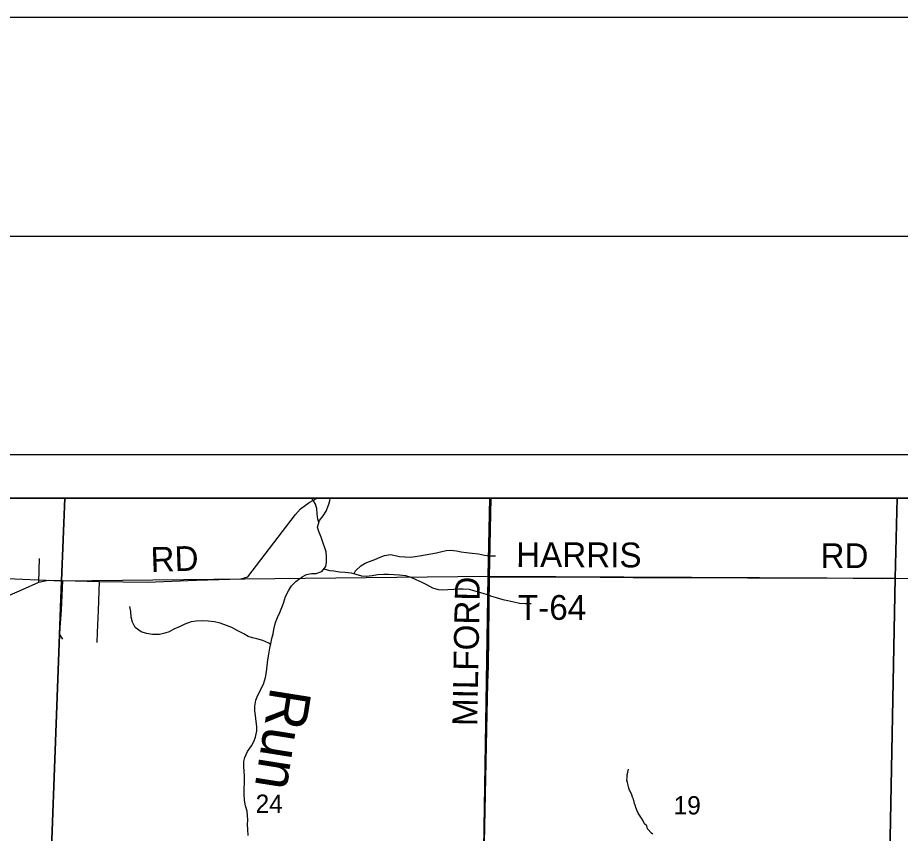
# Model space of a CAD drawing. Extents: x 0 to 34, y 0 to 22.
# Drawn here: x 5.004 to 7.025, y 20.132 to 22 of the extents above; entities that cross this region are included whole.
import ezdxf

# ---------------------------------------------------------------- set-up
doc = ezdxf.new("R2010")
doc.units = 0
for name, color, linetype in [('Default', 7, 'Continuous'), ('GM_X_Minor_River', 7, 'Continuous'), ('GM_X_Minor_River_Text', 7, 'Continuous'), ('GM_X_Section', 7, 'Continuous'), ('GM_X_Section_Text', 7, 'Continuous'), ('GM_X_Township_Road', 7, 'Continuous'), ('GM_X_Township_Road_Text', 7, 'Continuous'), ('SH_Border', 7, 'Continuous'), ('SH_Cut_Line', 7, 'Continuous'), ('SH_Data', 7, 'Continuous')]:
    doc.layers.add(name, color=color, linetype=linetype)

msp = doc.modelspace()

# ---------------------------------------------------------------- linework, layer by layer
at = {"layer": 'Default'}
msp.add_lwpolyline([(4.98, 17.7015), (5.0396, 17.6997), (5.1253, 17.6972), (5.2207, 17.6942), (5.2737, 17.6923), (5.3125, 17.691), (5.4195, 17.6873), (5.5532, 17.6849), (5.9893, 17.6676), (6.0568, 19.5343), (6.0632, 19.7108), (6.0696, 20.0002), (6.0777, 20.3704), (6.08, 20.4768), (6.0809, 20.5156), (6.0839, 20.7194), (6.0871, 20.9), (2.1, 20.9)], dxfattribs=at)
for points in [[(5.1123, 20.9), (4.1106, 20.9), (4.105, 20.7535), (5.1049, 20.7104)], [(6.0854, 20.9), (5.1123, 20.9), (5.1049, 20.7104), (6.0815, 20.7216)], [(8.9, 17.6104), (8.9, 20.9), (6.0871, 20.9), (6.0839, 20.7194), (6.0809, 20.5156), (6.08, 20.4768), (6.0777, 20.3704), (6.0696, 20.0002), (6.0632, 19.7108), (6.0568, 19.5343), (5.9893, 17.6676), (6.9889, 17.643), (7.0308, 17.6406), (8.0065, 17.6245)], [(7.0172, 20.9), (6.0854, 20.9), (6.0815, 20.7216), (7.0125, 20.7168)], [(8.0262, 20.9), (7.0172, 20.9), (7.0125, 20.7168), (8.0224, 20.7109)]]:
    msp.add_lwpolyline(points, close=True, dxfattribs=at)
at = {"layer": 'GM_X_Minor_River'}
for points in [[(5.694, 20.8445), (5.6916, 20.8515), (5.6896, 20.8637), (5.6888, 20.8759), (5.6861, 20.8858), (5.681, 20.8955), (5.6763, 20.9)], [(5.7103, 20.87), (5.7156, 20.8839), (5.7189, 20.894), (5.7193, 20.9)], [(5.5319, 20.1278), (5.5308, 20.1411), (5.5304, 20.1529), (5.531, 20.1635), (5.5305, 20.173), (5.5293, 20.1833), (5.5262, 20.1951), (5.5235, 20.2081), (5.5228, 20.2218), (5.5231, 20.2343), (5.5232, 20.2484), (5.5236, 20.2628), (5.5227, 20.2746), (5.5223, 20.2848), (5.5222, 20.2966), (5.5244, 20.3064), (5.5305, 20.3199), (5.5392, 20.333), (5.5452, 20.343), (5.5489, 20.3528), (5.5515, 20.3672), (5.5514, 20.377), (5.5502, 20.3888), (5.5487, 20.4025), (5.5475, 20.4132), (5.5471, 20.4238), (5.5493, 20.4371), (5.5542, 20.4491), (5.5674, 20.4738), (5.5717, 20.4892), (5.5739, 20.5024), (5.5755, 20.5161), (5.5766, 20.5297), (5.5789, 20.5429), (5.5819, 20.5561), (5.5837, 20.5667), (5.5863, 20.5784), (5.5889, 20.5893), (5.5907, 20.5995), (5.5946, 20.6154), (5.5991, 20.6267), (5.6047, 20.6383), (5.6092, 20.6495), (5.6125, 20.6597), (5.6175, 20.6744), (5.6239, 20.6875), (5.6311, 20.699), (5.6409, 20.709), (5.6552, 20.7196), (5.6656, 20.7254), (5.6771, 20.7274), (5.6877, 20.7275), (5.7004, 20.7321), (5.7094, 20.7436), (5.7116, 20.7534), (5.7116, 20.7659), (5.7104, 20.777), (5.7072, 20.7865), (5.7037, 20.7965), (5.6991, 20.8107), (5.6934, 20.8234), (5.6903, 20.8337), (5.6953, 20.8484), (5.7035, 20.8591), (5.7103, 20.87)], [(5.7747, 20.7271), (5.7779, 20.7337), (5.79, 20.7452), (5.7996, 20.751), (5.81, 20.7549), (5.8219, 20.7595), (5.8338, 20.7645), (5.8438, 20.7684), (5.8579, 20.7706), (5.8685, 20.7688), (5.8783, 20.7666), (5.8904, 20.7652), (5.9033, 20.7648), (5.914, 20.766), (5.9239, 20.7677), (5.9369, 20.77), (5.9498, 20.7723), (5.9628, 20.775), (5.9724, 20.7773), (5.9854, 20.7804), (5.9949, 20.7809), (6.0089, 20.7794), (6.0191, 20.7772), (6.0312, 20.7757), (6.0448, 20.7738), (6.0588, 20.7723), (6.0728, 20.7693), (6.0853, 20.7682), (6.0982, 20.7682)], [(5.7051, 20.7381), (5.7183, 20.7342), (5.7281, 20.7332), (5.7413, 20.7309), (5.7542, 20.7302), (5.7675, 20.7291), (5.7784, 20.7261), (5.7912, 20.722), (5.8018, 20.7213), (5.8155, 20.7228), (5.8277, 20.7248), (5.8422, 20.7255), (5.8528, 20.7256), (5.8661, 20.7252), (5.8782, 20.7245), (5.8919, 20.723), (5.9043, 20.7189), (5.9159, 20.7136), (5.9294, 20.7075), (5.9403, 20.7019), (5.9541, 20.6947), (5.9665, 20.6906), (5.9772, 20.6903), (5.989, 20.6911), (6.003, 20.6918), (6.0137, 20.6923), (6.0243, 20.6924), (6.0376, 20.6913), (6.0474, 20.6887), (6.0587, 20.6854), (6.0688, 20.6824), (6.0786, 20.6791), (6.0891, 20.6754), (6.0993, 20.6725), (6.1151, 20.6679), (6.1261, 20.6653), (6.1397, 20.6623), (6.1529, 20.6596), (6.1661, 20.6585), (6.1798, 20.6589)], [(5.5834, 20.565), (5.5796, 20.5676), (5.5657, 20.574), (5.5517, 20.5778), (5.5419, 20.58), (5.5322, 20.5833), (5.5217, 20.5889), (5.5086, 20.5965), (5.4944, 20.6037), (5.482, 20.6086), (5.4681, 20.6136), (5.4545, 20.6166), (5.4405, 20.6185), (5.428, 20.6192), (5.4128, 20.6185), (5.4017, 20.6165), (5.3867, 20.6116), (5.376, 20.6062), (5.3617, 20.5998), (5.3509, 20.594), (5.3413, 20.5905), (5.3287, 20.5874), (5.3128, 20.5878), (5.2996, 20.5897), (5.2867, 20.5935), (5.2734, 20.6037), (5.2669, 20.6161), (5.2645, 20.6275), (5.2634, 20.6401), (5.2614, 20.6519)], [(6.4581, 20.1304), (6.4555, 20.1328), (6.4459, 20.1426), (6.4442, 20.1495), (6.4394, 20.1539), (6.4358, 20.1612), (6.4322, 20.1675), (6.4246, 20.1788), (6.4221, 20.1842), (6.4207, 20.1877), (6.4189, 20.1919), (6.4187, 20.195), (6.4162, 20.2008), (6.4139, 20.2111), (6.4117, 20.215), (6.41, 20.2208), (6.4064, 20.2289), (6.405, 20.2316), (6.4036, 20.2359), (6.4016, 20.2428), (6.3999, 20.249), (6.3989, 20.2539), (6.3991, 20.26), (6.3997, 20.2661), (6.4005, 20.2691), (6.401, 20.2725), (6.4028, 20.2793)]]:
    msp.add_lwpolyline(points, dxfattribs=at)
at = {"layer": 'GM_X_Section'}
for points in [[(5.1049, 20.7104), (5.0674, 19.7096), (4.0623, 19.7415), (4.105, 20.7535)], [(6.0815, 20.7216), (6.0653, 19.7127), (5.0674, 19.7096), (5.1049, 20.7104)], [(6.0815, 20.7216), (7.0125, 20.7168), (6.9929, 19.6861), (6.0653, 19.7127)], [(7.0125, 20.7168), (8.0224, 20.7109), (7.9969, 19.6588), (6.9929, 19.6861)]]:
    msp.add_lwpolyline(points, close=True, dxfattribs=at)
at = {"layer": 'GM_X_Township_Road'}
msp.add_line((5.0527, 20.7079), (5.0542, 20.7619), dxfattribs=at)
for points in [[(4.9146, 20.6474), (5.0151, 20.6904), (5.0527, 20.7079), (5.0738, 20.7123), (5.1072, 20.7117), (5.1357, 20.7109), (5.1908, 20.7091), (5.3011, 20.7072), (5.4133, 20.7123), (5.516, 20.7155), (5.5313, 20.7199), (5.6403, 20.8625), (5.6515, 20.8758), (5.6714, 20.8899), (5.6897, 20.9)], [(6.0746, 20.2192), (6.0779, 20.3699), (6.0803, 20.4763), (6.0811, 20.5151), (6.0841, 20.7189), (6.0873, 20.9)], [(5.1072, 20.7117), (5.1037, 20.6438), (5.1009, 20.6036), (5.1003, 20.5881), (5.1071, 20.577)], [(5.1908, 20.7091), (5.1883, 20.6424), (5.1865, 20.5922), (5.1854, 20.5691)], [(6.0841, 20.7189), (6.2619, 20.7199), (6.413, 20.7179), (6.6752, 20.7173), (6.8495, 20.7171), (6.984, 20.7162), (7.1539, 20.7167), (7.3146, 20.715), (7.6263, 20.7154), (7.7448, 20.7148), (7.7708, 20.7143)], [(6.0635, 19.7103), (6.0698, 19.9997), (6.0746, 20.2192)]]:
    msp.add_lwpolyline(points, dxfattribs=at)
at = {"layer": 'SH_Border'}
msp.add_lwpolyline([(1.5, 21.5), (33.5, 21.5), (33.5, 0.5), (1.5, 0.5)], close=True, dxfattribs=at)
at = {"layer": 'SH_Cut_Line'}
msp.add_lwpolyline([(0, 0), (34, 0), (34, 22), (0, 22)], close=True, dxfattribs=at)
at = {"layer": 'SH_Data'}
for p, q in [((2, 21), (9, 21)), ((2.1, 20.9), (8.9, 20.9))]:
    msp.add_line(p, q, dxfattribs=at)

# ---------------------------------------------------------------- texts
at = {"layer": 'GM_X_Minor_River_Text'}
msp.add_text('Run', height=0.09467, rotation=260.9447, dxfattribs=at).set_placement((5.5835, 20.4698))
at = {"layer": 'GM_X_Section_Text'}
for s, p in [('24', (5.549, 20.1794)), ('19', (6.5057, 20.1758))]:
    msp.add_text(s, height=0.04186, rotation=0, dxfattribs=at).set_placement(p)
at = {"layer": 'GM_X_Township_Road_Text'}
for s, rotation, p in [('RD', 1.9757, (5.3095, 20.7306)), ('HARRIS', 359.813, (6.1452, 20.7423)), ('RD', 0, (6.8419, 20.7397)), ('MILFORD', 88.9307, (6.0562, 20.3777)), ('T-64', 0, (6.1494, 20.6213))]:
    msp.add_text(s, height=0.05682, rotation=rotation, dxfattribs=at).set_placement(p)

doc.saveas('drawing.dxf')
